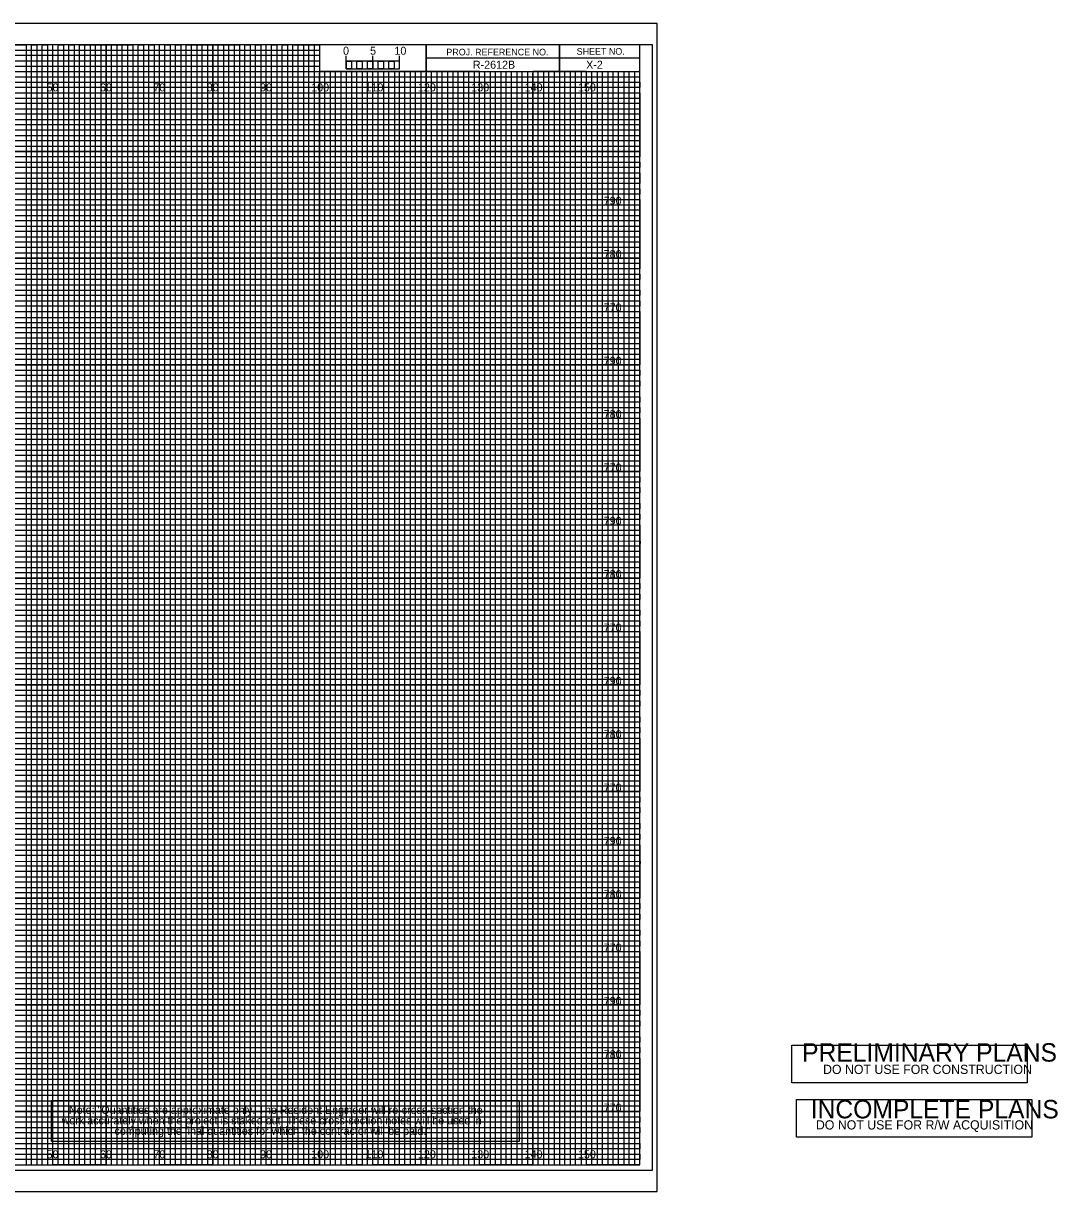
# Model space of a CAD drawing. Extents: x -13 to 398, y -5 to 214.
# Drawn here: x 204.5 to 398.3, y -5 to 214 of the extents above; entities that cross this region are included whole.
import ezdxf

# ---------------------------------------------------------------- set-up
doc = ezdxf.new("R2010")
doc.units = 0
for name, color, linetype in [('Exist Cross Section Cell', 7, 'Continuous'), ('Exist XS Center Line Elevation Label', 7, 'Continuous'), ('Exist XS Ground Line', 7, 'Continuous'), ('Prop XS Ditch Slope Text', 7, 'Continuous'), ('Prop XS Ditch Standard Text', 7, 'Continuous'), ('Prop XS Dump Level', 7, 'Continuous'), ('Prop XS Earthwork Shape', 7, 'Continuous'), ('Prop XS EOT Tick Mark', 7, 'Continuous'), ('Prop XS Finish Grade Earthwork', 7, 'Continuous'), ('Prop XS Finish Grade Paved Shoulder', 7, 'Continuous'), ('Prop XS Finish Grade Pavement', 7, 'Continuous'), ('Prop XS Guardrail', 7, 'Continuous'), ('Prop XS Hydro Fill Slope Data', 7, 'Continuous'), ('Prop XS Hydro Typical Ditch Data', 7, 'Continuous'), ('Prop XS Pvmt Edge Slope', 7, 'Continuous'), ('Prop XS SS Elevation Text', 7, 'Continuous'), ('Prop XS Subgrade Earthwork', 7, 'Continuous'), ('Prop XS Vertical Lines Alignments', 7, 'Continuous'), ('Prop XSC Text', 7, 'Continuous')]:
    doc.layers.add(name, color=color, linetype=linetype)

msp = doc.modelspace()

# ---------------------------------------------------------------- linework, layer by layer
at = {"layer": 'Exist XS Center Line Elevation Label'}
for points in [[(195, 210), (205, 210), (205, 0), (215, 0), (215, 210), (225, 210), (225, 0), (235, 0), (235, 210), (245, 210), (245, 0), (255, 0), (255, 210), (259.93, 210), (260, 210), (260, 205), (264.99, 205), (264.99, 0), (275, 0), (275, 205), (285, 205), (285, 0), (295, 0), (295, 205), (305, 205), (305, 0), (315, 0), (315, 205)], [(0, 205), (275, 205)], [(0, 185), (320, 185), (320, 195), (0, 195)], [(0, 165), (320, 165), (320, 175), (0, 175)], [(0, 145), (320, 145), (320, 155), (0, 155)], [(0, 125), (320, 125), (320, 135), (0, 135)], [(0, 105), (320, 105), (320, 115), (0, 115)], [(0, 85), (320, 85), (320, 95), (0, 95)], [(0, 65), (320, 65), (320, 75), (0, 75)], [(0, 45), (320, 45), (320, 55), (0, 55)], [(0, 25), (320, 25), (320, 35), (0, 35)], [(0, 5), (320, 5), (320, 15), (0, 15)]]:
    msp.add_lwpolyline(points, dxfattribs=at)
at = {"layer": 'Exist XS Ground Line'}
for p, q in [((210, 210), (200, 210)), ((210, 0), (210, 210)), ((230, 210), (220, 210)), ((220, 210), (220, 0)), ((230, 0), (230, 210)), ((250, 210), (240, 210)), ((240, 210), (240, 0)), ((250, 0), (250, 210)), ((260, 210), (260, 0)), ((270, 0), (270, 205)), ((290, 205), (280, 205)), ((280, 205), (280, 0)), ((290, 0), (290, 205)), ((310, 205), (300, 205)), ((300, 205), (300, 0)), ((310, 0), (310, 205)), ((220, 0), (210, 0)), ((240, 0), (230, 0)), ((260, 0), (250, 0)), ((280, 0), (270, 0)), ((300, 0), (290, 0)), ((320, 0), (310, 0)), ((320, 0), (320, 0))]:
    msp.add_line(p, q, dxfattribs=at)
for points in [[(0, 200), (320, 200), (320, 190), (0, 190)], [(0, 180), (320, 180), (320, 170), (0, 170)], [(0, 160), (320, 160), (320, 150), (0, 150)], [(0, 140), (320, 140), (320, 130), (0, 130)], [(0, 120), (320, 120), (320, 110), (0, 110)], [(0, 100), (320, 100), (320, 90), (0, 90)], [(0, 80), (320, 80), (320, 70), (0, 70)], [(0, 60), (320, 60), (320, 50), (0, 50)], [(0, 40), (320, 40), (320, 30), (0, 30)], [(0, 20), (320, 20), (320, 10), (0, 10)]]:
    msp.add_lwpolyline(points, dxfattribs=at)
at = {"layer": 'Prop XS Ditch Slope Text'}
for p, q in [((267, 205), (266.01, 205)), ((266.01, 205), (266.01, 0)), ((267, 0), (267, 205)), ((269, 205), (268, 205)), ((268, 205), (268, 0)), ((269, 0), (269, 205)), ((266.01, 0), (265, 0)), ((268, 0), (267, 0))]:
    msp.add_line(p, q, dxfattribs=at)
for points in [[(205, 0), (206, 0), (206, 210), (207, 210), (207, 0)], [(207, 0), (208, 0), (208, 210), (209, 210), (209, 0)], [(210, 0), (211, 0), (211, 210), (212, 210), (212, 0)], [(212, 0), (213, 0), (213, 210), (214, 210), (214, 0)], [(215, 0), (216, 0), (216, 210), (217, 210), (217, 0)], [(217, 0), (218, 0), (218, 210), (219, 210), (219, 0)], [(220, 0), (221, 0), (221, 210), (222, 210), (222, 0)], [(222, 0), (223, 0), (223, 210), (224, 210), (224, 0)], [(225, 0), (226, 0), (226, 210), (227, 210), (227, 0)], [(227, 0), (228, 0), (228, 210), (229, 210), (229, 0)], [(230, 0), (231, 0), (231, 210), (232, 210), (232, 0)], [(232, 0), (233, 0), (233, 210), (234, 210), (234, 0)], [(235, 0), (236, 0), (236, 210), (237, 210), (237, 0)], [(237, 0), (238, 0), (238, 210), (239, 210), (239, 0)], [(240, 0), (241, 0), (241, 210), (242, 210), (242, 0)], [(242, 0), (243, 0), (243, 210), (244, 210), (244, 0)], [(245, 0), (246, 0), (246, 210), (247, 210), (247, 0)], [(247, 0), (248, 0), (248, 210), (249, 210), (249, 0)], [(250, 0), (251, 0), (251, 210), (252, 210), (252, 0)], [(252, 0), (253, 0), (253, 210), (254, 210), (254, 0)], [(255, 0), (256, 0), (256, 210), (257, 210), (257, 0)], [(257, 0), (258, 0), (258, 210), (259, 210), (259, 0)], [(260, 0), (261, 0), (261, 205), (262.02, 205), (262.02, 0)], [(262, 0), (263, 0), (263, 205), (263.99, 205), (263.99, 0)], [(270, 0), (270.98, 0), (270.98, 205), (272, 205), (272, 0)], [(272, 0), (273, 0), (273, 205), (274.05, 205), (274.05, 0)], [(275, 0), (276, 0), (276, 205), (277, 205), (277, 0)], [(277, 0), (278, 0), (278, 205), (279, 205), (279, 0)], [(280, 0), (281, 0), (281, 205), (282, 205), (282, 0)], [(282, 0), (283, 0), (283, 205), (284, 205), (284, 0)], [(285, 0), (286, 0), (286, 205), (287, 205), (287, 0)], [(287, 0), (288, 0), (288, 205), (289, 205), (289, 0)], [(290, 0), (291, 0), (291, 205), (292, 205), (292, 0)], [(292, 0), (293, 0), (293, 205), (294, 205), (294, 0)], [(295, 0), (296, 0), (296, 205), (297, 205), (297, 0)], [(297, 0), (298, 0), (298, 205), (299, 205), (299, 0)], [(300, 0), (301, 0), (301, 205), (302, 205), (302, 0)], [(302, 0), (303, 0), (303, 205), (304, 205), (304, 0)], [(305, 0), (306, 0), (306, 205), (307, 205), (307, 0)], [(307, 0), (308, 0), (308, 205), (309, 205), (309, 0)], [(310, 0), (311, 0), (311, 205), (312, 205), (312, 0)], [(312, 0), (313, 0), (313, 205), (314, 205), (314, 0)], [(315, 0), (316, 0), (316, 205), (317, 205), (317, 0)], [(317, 0), (318, 0), (318, 205), (319, 205), (319, 0)]]:
    msp.add_lwpolyline(points, dxfattribs=at)
at = {"layer": 'Prop XS Ditch Standard Text'}
for p, q in [((305, 210), (305, 205)), ((305, 205), (305, 210)), ((280, 207.5), (280, 205)), ((320, 207.49), (280, 207.49)), ((280, 205), (320, 205))]:
    msp.add_line(p, q, dxfattribs=at)
for points in [[(320, 210), (0, 210), (0, 0), (320, 0)], [(280, 210), (260, 210), (260, 205.03), (280, 205.03)], [(320, 210), (280, 210), (280, 205), (320, 205)]]:
    msp.add_lwpolyline(points, close=True, dxfattribs=at)
at = {"layer": 'Prop XS Dump Level'}
for p, q in [((0, 209), (260, 209)), ((260, 209), (260, 207.98)), ((260, 207.98), (0, 207.98)), ((0, 207), (260, 207)), ((260, 205.89), (0, 205.89)), ((260, 207), (260, 205.89)), ((0, 204), (320, 204))]:
    msp.add_line(p, q, dxfattribs=at)
for points in [[(0, 203), (270, 203), (320, 203), (320, 202), (0, 202)], [(0, 201), (320, 201), (320, 199), (0, 199)], [(0, 198), (320, 198), (320, 197), (0, 196.98)], [(0, 196), (320, 196), (320, 194), (0, 194)], [(0, 193), (320, 193), (320, 192), (0, 192)], [(0, 191), (320, 191), (320, 189), (0, 189)], [(0, 188), (320, 188), (320, 187), (0, 187)], [(0, 186), (320, 186), (320, 184), (0, 184)], [(0, 183), (320, 183), (320, 182), (0, 182)], [(0, 181), (320, 181), (320, 179), (0, 179)], [(0, 178), (320, 178), (320, 177), (0, 177)], [(0, 176), (320, 176), (320, 173.95), (320, 173), (320, 172), (0, 172)], [(0, 174), (320, 174), (320, 173), (0, 173)], [(0, 171), (320, 171), (320, 169), (0, 169.03)], [(0, 169.03), (320, 169), (320, 168), (0, 168)], [(0, 167), (320, 167), (320, 166), (0, 166)], [(0, 164), (320, 164), (320, 163), (0, 163)], [(0, 162), (320, 162), (320, 161), (0, 161)], [(-0.07, 158.89), (320, 158.89), (320, 157.88), (-0.07, 157.88)], [(0, 157), (320, 157), (320, 156), (0, 156)], [(0, 154), (320, 154), (320, 153), (0, 153)], [(0, 152), (320, 152), (320, 151), (0, 151)], [(0, 149), (320, 149), (320, 148), (0, 148)], [(0, 147), (320, 147), (320, 146), (0, 146)], [(0, 144), (320, 144), (320, 143), (0, 143)], [(0, 142), (320, 142), (320, 141), (0, 141)], [(0, 139), (320, 139), (319.99, 137.98), (0, 138)], [(0, 137), (320, 137), (320, 136), (0, 136)], [(0, 134), (320, 134), (320, 133), (0, 133)], [(0, 132), (320, 132), (320, 131), (0, 131)], [(0, 129), (320, 129), (320, 128), (0, 128)], [(0, 127), (320, 127), (320, 126), (0, 126)], [(0, 124), (320, 124), (320, 123), (0, 123)], [(0, 122), (320, 122), (320, 121), (0, 121)], [(0, 119), (320, 119), (320, 118), (0, 118)], [(0, 116.99), (320.07, 116.91), (320, 116), (0, 116)], [(0, 114), (320, 114), (320, 113), (0, 113)], [(0, 112), (320, 112), (320, 111), (0, 111)], [(0, 109), (320, 109), (320, 108), (0, 108)], [(0, 107), (320, 107), (320, 106), (0, 106)], [(0, 104), (320, 104), (320, 103), (0, 103)], [(0, 102), (320, 102), (320, 101), (0, 101)], [(0, 99), (320, 99), (320, 98), (0, 98)], [(0, 97), (320, 97), (320, 96), (0, 96)], [(0, 94), (320, 94), (320, 93), (0, 93)], [(0, 92), (320, 92), (320, 91), (0, 91)], [(0, 89), (320, 89), (320, 88), (0, 88)], [(0, 87), (320, 87), (320, 86), (0, 86)], [(0, 84), (320, 84), (320, 83), (0, 83)], [(0, 82), (320, 82), (320, 81), (0, 81)], [(0, 79), (320, 79), (319.99, 77.98), (0, 78)], [(0, 77), (320, 77), (320, 76), (0, 76)], [(0, 74), (320, 74), (320, 73), (0, 73)], [(0, 72), (320, 72), (320, 71), (0, 71)], [(0, 69), (320, 69), (320, 68), (0, 68)], [(0, 67), (320, 67), (320, 66), (0, 66)], [(0, 64), (320, 64), (320, 63), (0, 63)], [(0, 62), (320, 62), (320, 61), (0, 61)], [(0, 59), (320, 59), (320, 58), (0, 58)], [(0, 56.99), (320.07, 56.91), (320, 56), (0, 56)], [(0, 54), (320, 54), (320, 53), (0, 53)], [(0, 52), (320, 52), (320, 51), (0, 51)], [(0, 49), (320, 49), (320, 48), (0, 48)], [(0, 47), (320, 47), (320, 46), (0, 46)], [(0, 44), (320, 44), (320, 43), (0, 43)], [(0, 42), (320, 42), (320, 41), (0, 41)], [(0, 39), (320, 39), (320, 38), (0, 38)], [(0, 37), (320, 37), (320, 36), (0, 36)], [(0, 34), (320, 34), (320, 33), (0, 33)], [(0, 32), (320, 32), (320, 31), (0, 31)], [(0, 29), (320, 29), (320, 28), (0, 28)], [(0, 27), (320, 27), (320, 26), (0, 26)], [(0, 24), (320, 24), (320, 23), (0, 23)], [(0, 22), (320, 22), (320, 21), (0, 21)], [(0, 19), (320, 19), (320, 18), (0, 18)], [(0, 17), (320, 17), (320, 16), (0, 16)], [(0, 14), (320, 14), (320, 13), (0, 13)], [(0, 12), (320, 12), (320, 11), (0, 11)], [(0, 9), (320, 9), (320, 8), (0, 8)], [(0, 7), (320, 7), (320, 6), (0, 6)], [(0, 4), (320, 4), (320, 3), (0, 3)], [(0, 2), (320, 2), (320, 1), (0, 1)]]:
    msp.add_lwpolyline(points, dxfattribs=at)
at = {"layer": 'Prop XS Earthwork Shape'}
msp.add_lwpolyline([(209.76, 12.07), (297.43, 12.07), (297.43, 4.38), (209.76, 4.38)], close=True, dxfattribs=at)
at = {"layer": 'Prop XS EOT Tick Mark'}
for p, q in [((210, 0), (210, 210)), ((220, 0), (220, 210)), ((230, 0), (230, 210)), ((240, 0), (240, 210)), ((250, 0), (250, 210)), ((260, 0), (260, 204.69)), ((270, 0), (270, 204.69)), ((280, 0), (280, 204.69)), ((290, 0), (290, 204.69)), ((300, 0), (300, 204.69)), ((310, 0), (310, 204.69)), ((0, 200), (320, 200)), ((0, 190), (320, 190)), ((0, 180), (320, 180)), ((0, 170), (320, 170)), ((0, 160), (320, 160)), ((0, 150), (320, 150)), ((0, 140), (320, 140)), ((0, 130), (320, 130)), ((0, 120), (320, 120)), ((0, 110), (320, 110)), ((0, 100), (320, 100)), ((0, 90), (320, 90)), ((0, 80), (320, 80)), ((0, 70), (320, 70)), ((0, 60), (320, 60)), ((0, 50), (320, 50)), ((0, 40), (320, 40)), ((0, 30), (320, 30)), ((0, 20), (320, 20)), ((0, 10), (320, 10))]:
    msp.add_line(p, q, dxfattribs=at)
at = {"layer": 'Prop XS Finish Grade Pavement'}
msp.add_lwpolyline([(-13.4, -5), (323.3, -5), (323.3, 214), (-13.4, 214)], close=True, dxfattribs=at)
at = {"layer": 'Prop XS Guardrail'}
msp.add_lwpolyline([(348.48, 15.42), (348.48, 22.47), (392.58, 22.47), (392.58, 15.42)], close=True, dxfattribs=at)
at = {"layer": 'Prop XS Pvmt Edge Slope'}
for p, q in [((323.3, 214), (-13.4, 214)), ((-13.4, -5), (323.3, -5))]:
    msp.add_line(p, q, dxfattribs=at)
at = {"layer": 'Prop XS SS Elevation Text'}
for p, q in [((265, 205.49), (265, 207.9)), ((265, 206.9), (265, 207.9)), ((270, 205.49), (270, 207.9)), ((275, 205.49), (275, 207.9)), ((275, 206.9), (275, 207.9))]:
    msp.add_line(p, q, dxfattribs=at)
for points in [[(275, 206.9), (265, 206.9), (265, 205.49), (275, 205.49)], [(265, 206.9), (266, 206.9), (266, 205.49), (265, 205.49)], [(267, 206.9), (268, 206.9), (268, 205.49), (267, 205.49)], [(269, 206.9), (270, 206.9), (270, 205.49), (269, 205.49)], [(271, 206.9), (272, 206.9), (272, 205.49), (271, 205.49)], [(273, 206.9), (274, 206.9), (274, 205.49), (273, 205.49)]]:
    msp.add_lwpolyline(points, close=True, dxfattribs=at)
at = {"layer": 'Prop XS Subgrade Earthwork'}
msp.add_lwpolyline([(-10.8, -1), (322.4, -1), (322.4, 210), (-10.8, 210)], close=True, dxfattribs=at)
at = {"layer": 'Prop XS Vertical Lines Alignments'}
msp.add_lwpolyline([(349.36, 5.22), (349.36, 12.27), (393.46, 12.27), (393.46, 5.22)], close=True, dxfattribs=at)

# ---------------------------------------------------------------- texts
at = {"layer": 'Exist Cross Section Cell'}
for s, p in [('50', (208.86, 201.25)), ('60', (218.86, 201.25)), ('70', (228.86, 201.25)), ('80', (238.86, 201.25)), ('90', (248.86, 201.25)), ('100', (258.44, 201.25)), ('110', (268.62, 201.25)), ('120', (278.44, 201.25)), ('130', (288.44, 201.25)), ('140', (298.44, 201.25)), ('150', (308.44, 201.25)), ('50', (208.86, 1.25)), ('60', (218.86, 1.25)), ('70', (228.86, 1.25)), ('80', (238.86, 1.25)), ('90', (248.86, 1.25)), ('100', (258.44, 1.25)), ('110', (268.62, 1.25)), ('120', (278.44, 1.25)), ('130', (288.44, 1.25)), ('140', (298.44, 1.25)), ('150', (308.44, 1.25))]:
    msp.add_text(s, height=1.5, dxfattribs=at).set_placement(p)
at = {"layer": 'Prop XS Ditch Standard Text'}
for s, p in [('PROJ. REFERENCE NO.', (283.77, 207.99)), ('SHEET NO.', (308.19, 208.12))]:
    msp.add_text(s, height=1.25, dxfattribs=at).set_placement(p)
at = {"layer": 'Prop XS Finish Grade Earthwork'}
msp.add_text('X-2', height=1.5, dxfattribs=at).set_placement((309.96, 205.5))
at = {"layer": 'Prop XS Finish Grade Paved Shoulder'}
for s, p in [('790', (313.26, 180)), ('780', (313.26, 170)), ('770', (313.26, 160)), ('790', (313.26, 150)), ('780', (313.26, 140)), ('770', (313.26, 130)), ('790', (313.26, 120)), ('780', (313.26, 110)), ('770', (313.26, 100)), ('790', (313.26, 90)), ('780', (313.26, 80)), ('770', (313.26, 70)), ('790', (313.26, 60)), ('780', (313.26, 50)), ('770', (313.26, 40)), ('790', (313.26, 30)), ('780', (313.26, 20)), ('770', (313.26, 10))]:
    msp.add_text(s, height=1.5, dxfattribs=at).set_placement(p)
at = {"layer": 'Prop XS Guardrail'}
for s, height, p in [('PRELIMINARY PLANS', 3.456, (350.43, 19.37)), ('DO NOT USE FOR CONSTRUCTION', 1.728, (354.36, 17.06))]:
    msp.add_text(s, height=height, dxfattribs=at).set_placement(p)
at = {"layer": 'Prop XS Hydro Fill Slope Data'}
for s, p in [('5', (269.47, 208.12)), ('10', (274.04, 208.12))]:
    msp.add_text(s, height=1.5, dxfattribs=at).set_placement(p)
at = {"layer": 'Prop XS Hydro Typical Ditch Data'}
msp.add_text('R-2612B', height=1.5, dxfattribs=at).set_placement((288.74, 205.5))
at = {"layer": 'Prop XS SS Elevation Text'}
msp.add_text('0', height=1.5, dxfattribs=at).set_placement((264.41, 208.12))
at = {"layer": 'Prop XS Vertical Lines Alignments'}
for s, height, p in [('INCOMPLETE PLANS', 3.456, (352.05, 8.73)), ('DO NOT USE FOR R/W ACQUISITION', 1.728, (353.02, 6.65))]:
    msp.add_text(s, height=height, dxfattribs=at).set_placement(p)
at = {"layer": 'Prop XSC Text'}
for s, p in [('Note: "Quantities are approximate only. The Resident Engineer will re-cross-section the', (213.04, 9.57)), ('work accurately when the project is staked out. These cross-section notes will be used in', (211.67, 7.61)), ('computing the final quantities for which the contractor will be paid."', (221.58, 5.64))]:
    msp.add_text(s, height=1.5, dxfattribs=at).set_placement(p)

doc.saveas('drawing.dxf')
